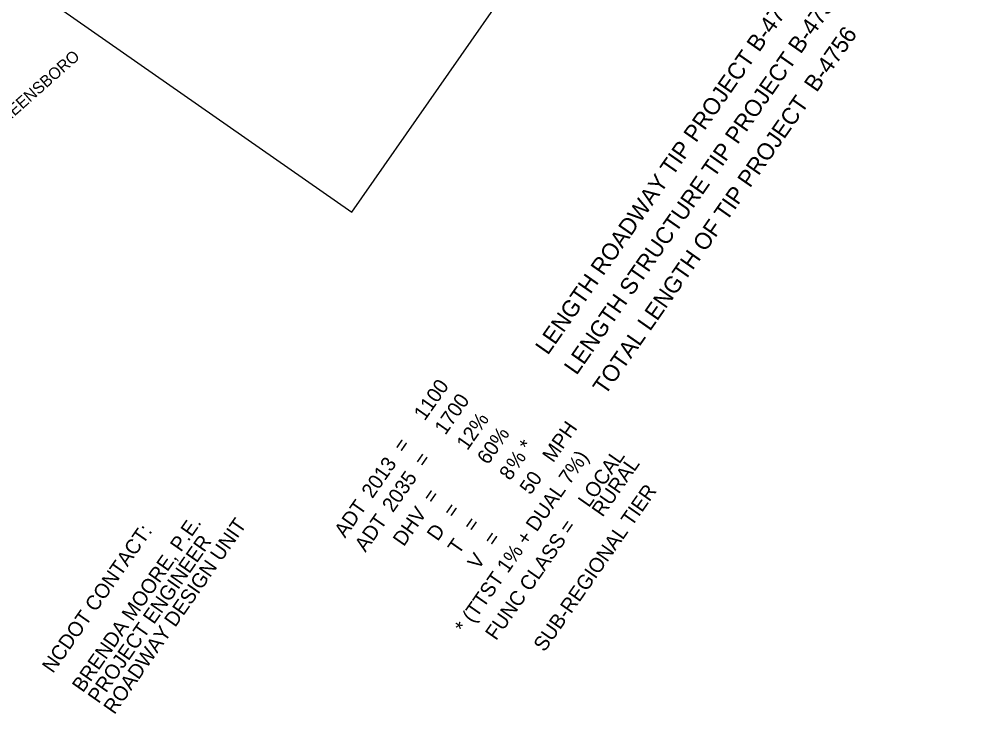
# Model space of a CAD drawing. Extents: x 1731327 to 1735374, y 884856 to 889832.
# Drawn here: x 1731919 to 1732491, y 884856 to 885272 of the extents above; entities that cross this region are included whole.
import ezdxf

# ---------------------------------------------------------------- set-up
doc = ezdxf.new("R2010")
doc.units = 0
for name, color, linetype in [('Exist Horizontal Baseline Alignment', 7, 'Continuous'), ('Exist Horizontal Baseline Alignment Station Label', 7, 'Continuous'), ('Exist Other Culture Area Outline', 7, 'Continuous'), ('Exist Other Culture Sign CELL', 7, 'Continuous'), ('Exist Property Iron Pin CELL', 7, 'Continuous')]:
    doc.layers.add(name, color=color, linetype=linetype)

msp = doc.modelspace()

# ---------------------------------------------------------------- linework, layer by layer
at = {"layer": 'Exist Other Culture Area Outline'}
msp.add_lwpolyline([(1732238.91, 886072.74), (1731769.46, 885400.02), (1732118.14, 885156.7), (1732587.59, 885829.41)], close=True, dxfattribs=at)

# ---------------------------------------------------------------- texts
at = {"layer": 'Exist Horizontal Baseline Alignment'}
msp.add_text('TO GREENSBORO', height=7, rotation=41.5166, dxfattribs=at).set_placement((1731893.66, 885194.24))
at = {"layer": 'Exist Horizontal Baseline Alignment Station Label'}
for s, p in [('1100 ', (1732161.85, 885031.13)), ('1700 ', (1732174.2, 885022.53)), ('12%', (1732187.4, 885013.33)), ('60%', (1732199.75, 885004.73)), ('MPH', (1732238.88, 885005.98)), ('=', (1732149.52, 885011.71)), ('% *', (1732217.16, 885001.32)), ('2013', (1732130.47, 884984.52)), ('=', (1732161.82, 885003.12)), ('LOCAL', (1732260.26, 884979.09)), ('8', (1732213.05, 884995.23)), ('RURAL', (1732268.46, 884973.37)), ('2035', (1732142.78, 884976.11)), ('50', (1732225.27, 884986.71)), ('=', (1732167.08, 884981.29)), ('ADT', (1732114.11, 884960.88)), ('DHV', (1732149.26, 884955.75)), ('=', (1732179.39, 884972.71)), ('ADT', (1732126.34, 884952.36)), ('=', (1732191.37, 884964.34)), ('FUNC CLASS = ', (1732204.64, 884899.39)), ('D', (1732169.63, 884958.9)), ('=', (1732203.66, 884955.77)), ('T', (1732182.22, 884950.91)), ('V', (1732194.05, 884941.82))]:
    msp.add_text(s, height=8.75, rotation=55.0911, dxfattribs=at).set_placement(p)
at = {"layer": 'Exist Other Culture Sign CELL'}
for s, p in [('* (TTST 1% + DUAL 7%)', (1732186.36, 884903.44)), ('SUB-REGIONAL TIER', (1732233.6, 884892.52)), ('BRENDA MOORE, P.E.', (1731956.93, 884868.19)), ('ROADWAY DESIGN UNIT', (1731975.75, 884855.06)), ('NCDOT CONTACT:', (1731939, 884879.72)), ('PROJECT ENGINEER', (1731966.34, 884861.63))]:
    msp.add_text(s, height=8.7501, rotation=55.0911, dxfattribs=at).set_placement(p)
at = {"layer": 'Exist Property Iron Pin CELL'}
for s, p in [('LENGTH ROADWAY TIP PROJECT B-4756', (1732235.64, 885070.46)), ('LENGTH STRUCTURE TIP PROJECT B-4756', (1732252.87, 885058.44)), ('TOTAL LENGTH OF TIP PROJECT  B-4756', (1732270.1, 885046.41))]:
    msp.add_text(s, height=10, rotation=55.0911, dxfattribs=at).set_placement(p)

doc.saveas('drawing.dxf')
